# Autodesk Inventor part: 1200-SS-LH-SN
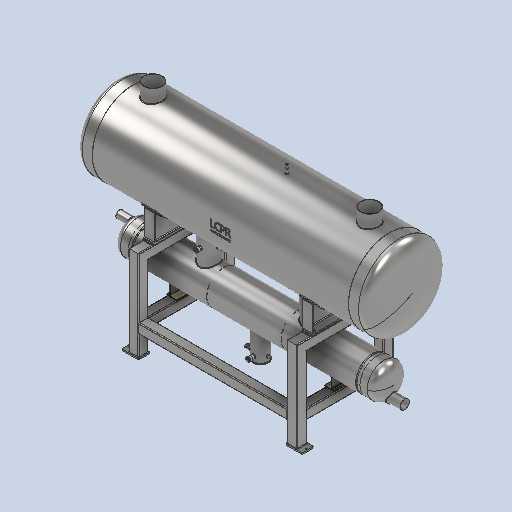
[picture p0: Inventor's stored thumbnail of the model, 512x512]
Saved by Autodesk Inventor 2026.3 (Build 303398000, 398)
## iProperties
Created: 2026-05
Part Number: 1200-SS-LH-SN
Material: Generic
Document SubType Name: Modeling
Designer: rva
Density: 1 g/cm^3
Appearance: Default
Author: rva
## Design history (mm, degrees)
derived "LCPR-SS-1200-LH-SN.iam"
body "Solid1"
node "Sub-SS-500-250-3326-294-125-100-LH.iam:1::LCPR-SS-500 mm Sub"
node "Sub-SS-500-250-3326-294-125-100-LH.iam:1::LCPR-SS-500 mm Sub"
node "Sub-SS-500-250-3326-294-125-100-LH.iam:1::H1100-R.ipt:1"
node "Sub-SS-500-250-3326-294-125-100-LH.iam:1::1-2 Inch NPT Socke"
node "Sub-SS-500-250-3326-294-125-100-LH.iam:1::Welds"
node "Sub-SS-500-250-3326-294-125-100-LH.iam:1::200 mm Oil Pot Ass"
node "LCPR-SS-1200-Frame Assembly.iam:1::LCPR-SS_170 x 250 Foot Pl"
node "LCPR-SS-1200-Frame Assembly.iam:1::LCPR-SS_170 x 250 Foot Pl"
node "LCPR-SS-1200-Frame Assembly.iam:1::LCPR-SS_170 x 250 Foot Pl"
node "LCPR-SS-1200-Frame Assembly.iam:1::LCPR-SS_170 x 250 Foot Pl"
node "LCPR-SS-1200-Frame Assembly.iam:1::Welds"
node "AS 1112 - M20(2).ipt:1"
node "AS 1237 (4.2) 20 mm:1"
node "AS 1111 - Metric M20 x 200:1"
node "AS 1112 - M20(2).ipt:2"
node "AS 1237 (4.2) 20 mm:3"
node "AS 1111 - Metric M20 x 200:2"
node "AS 1112 - M20(2).ipt:3"
node "AS 1237 (4.2) 20 mm:5"
node "AS 1111 - Metric M20 x 200:3"
node "AS 1112 - M20(2).ipt:4"
node "AS 1237 (4.2) 20 mm:7"
node "AS 1111 - Metric M20 x 200:4"
node "Nylon Heat Tranfer Spacer 1028 x 150.ipt:1"
node "Nylon Heat Tranfer Spacer 1028 x 150.ipt:2"
node "LCPR-SS-1200-3800-250-SN-WELD.iam:1::LCPR-LOGO.ipt:1"
node "LCPR-SS-1200-3800-250-SN-WELD.iam:1::H1100-R.ipt:1"
node "LCPR-SS-1200-3800-250-SN-WELD.iam:1::1200 mm-SS-Dome End Cap"
node "LCPR-SS-1200-3800-250-SN-WELD.iam:1::LCPR-SS-1200-Leg Assemb"
node "LCPR-SS-1200-3800-250-SN-WELD.iam:1::LCPR-SS-1200-Leg Assemb"
node "LCPR-SS-1200-3800-250-SN-WELD.iam:1::1200 mm-SS-Dome End Cap"
node "LCPR-SS-1200-3800-250-SN-WELD.iam:1::Welds"
node "Nylon Heat Tranfer Spacer 300 x 150.ipt:1"
node "Nylon Heat Tranfer Spacer 300 x 150.ipt:2"
node "LCPR-SS-1200-LH-SN.iam_Bodies"
